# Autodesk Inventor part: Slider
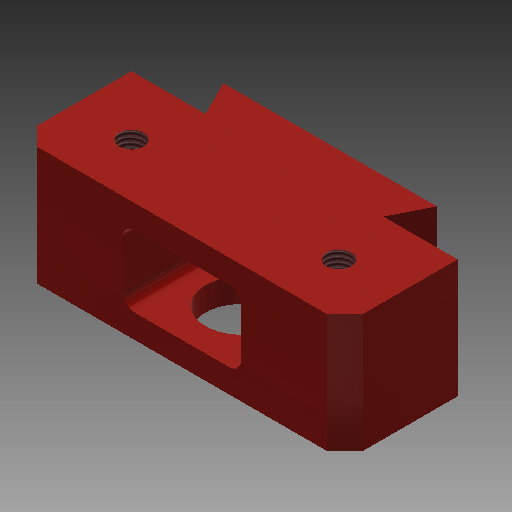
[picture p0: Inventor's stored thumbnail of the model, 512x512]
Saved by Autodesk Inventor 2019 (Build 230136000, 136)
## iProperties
Created: 2011-02
Part Number: Slider
Material: Glass
Document SubType Name: Modeling
Designer: landrews
Density: 2.18 g/cm^3
Appearance: Orange-Red
Mass: 44.0724 g
Surface Area: 68.5197 cm^2
Volume: 20.2167 cm^3
Author: landrews
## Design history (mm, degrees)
sketch "Sketch1"
  geometry: L1 (-27.5, 6)-(-15, 6); L2 (-15, 6)-(-18, 0); L3 (-27.5, 25)-(-27.5, 6); L4 (-27.5, 25)-(0, 25); L5 (-18, 0)-(0, 0); L6 (0, -5)-(0, 30) reference; L7 (38.5, 0)-(-38.5, 0) reference; L8 (27.5, 6)-(15, 6); L9 (15, 6)-(18, 0); L10 (27.5, 25)-(27.5, 6); L11 (27.5, 25)-(0, 25); L12 (18, 0)-(0, 0)
  constraints: 20 end point, 4 symmetric about line, 3 point on line, 2 horizontal
  dimensions: "d9" = 19 distance of L3.start L1.start; "d10" = 25 distance between parallel lines of L5 L4; "d11" = 27.5 distance between parallel lines of L6 L3; "d17" = 12.5 distance of L1.start L1.end; "d19" = 9.5 distance from line of L3 L2.end
extrude "Extrusion1" new body sketch "Sketch1" stored distance "d13" = 20; taper "d14" = 0 deg
sketch "Sketch2"
  geometry: L1 (18, 0)-(-18, 0) reference; L2 (-27.5, 25)-(27.5, 25) reference; 3 further points
  constraints: 1 midpoint, 1 vertical alignment
  dimensions: "d20" = 10 distance from line of L2 point (0, 15)
hole "Hole1" sketch "Sketch2" at (0, 15) diameter "d21" = 12; stored, may be unused: countersink angle "d25" = 90 deg, drill point angle "d27" = 118 deg; dims "d22" = 6, "d23" = 4, "d24" = 2, "d26" = 8
sketch "Sketch3"
  geometry: L1 (19.5, -16)-(35.5, -16); L2 (35.5, -4)-(19.5, -4); L3 (37.5, -14)-(37.5, -6); L4 (17.5, -6)-(17.5, -14); L5 (-11, -10)-(66, -10) reference; L6 (27.5, 4)-(27.5, -24) reference; A1 r 2 centre (35.5, -14) between (35.5, -16) and (37.5, -14); A2 r 2 centre (35.5, -6) between (37.5, -6) and (35.5, -4); A3 r 2 centre (19.5, -6) between (19.5, -4) and (17.5, -6); A4 r 2 centre (19.5, -14) between (17.5, -14) and (19.5, -16); 3 further points
  constraints: 8 end point, 8 point on circle, 8 tangent, 4 centre point, 3 equal radius, 2 midpoint, 2 parallel, 1 horizontal, 1 horizontal alignment, 1 perpendicular, 1 vertical alignment, 2 other
  dimensions: "d28" = 2 radius of A4; "d29" = 20 distance between parallel lines of L3 L4; "d30" = 12 distance between parallel lines of L1 L2
extrude "Extrusion2" cut sketch "Sketch3" distance "d35" = 16; taper "d36" = 0 deg
sketch "Sketch4"
  geometry: L1 (27.5, -25)-(-27.5, -25) reference; L2 (27.5, -6)-(27.5, -25) reference; L3 (-27.5, -25)-(-27.5, -6) reference; 3 further points
  constraints: 1 horizontal alignment
  dimensions: "d37" = 10 distance from line of L3 point (-17.5, -16); "d38" = 9 distance from line of L1 point (-17.5, -16); "d39" = 10 distance from line of L2 point (17.5, -16) (= d37)
hole "Hole2" sketch "Sketch4" at (-17.5, -16), (17.5, -16) diameter "d40" = 4.134; stored, may be unused: countersink angle "d44" = 90 deg, drill point angle "d46" = 118 deg; dims "d41" = 6, "d42" = 4, "d43" = 2, "d45" = 8
chamfer "Chamfer1" distance "d47" = 3; stored, may be unused: second distance "d48" = 2, angle "d49" = 45 deg
body "Solid1"
other parameters: "d3" = 0.5 [user parameter], "d4" = 25 [user parameter]
